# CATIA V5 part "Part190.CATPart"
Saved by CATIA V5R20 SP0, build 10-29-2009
Part number: FA 168700-3
Revision: ANY
Definition: UNKNOWN
Nomenclature: FA 168700-3
Source: Unknown
Bounding box of the stored display mesh (mm): x -3 to 3, y 0 to 4.95, z -3.464 to 3.464
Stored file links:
  C:\Users\Utente\Desktop\IO LAVORO\3D X SITO CF\CUMSA\3D files FA\FA 168700\Part190.CATPart
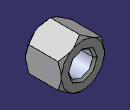
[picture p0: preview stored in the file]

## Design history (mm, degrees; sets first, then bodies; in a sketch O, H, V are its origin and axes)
Body1 "Cortar-Extruir3" (main body)
  Solid1: solid without history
